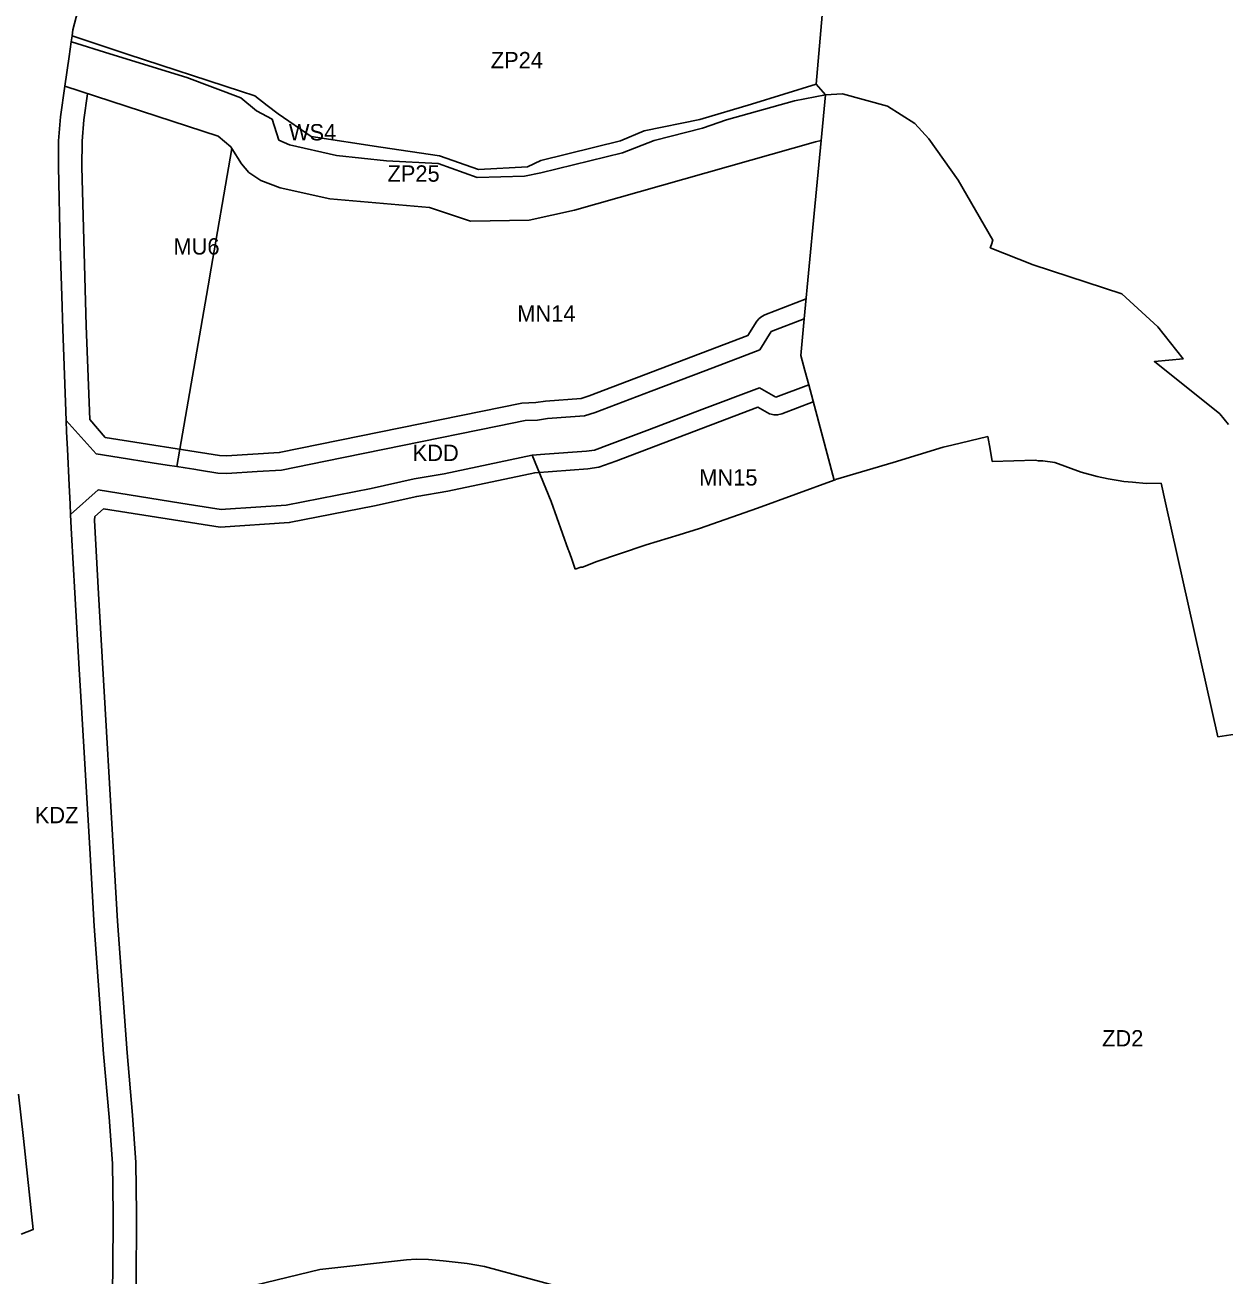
# Model space of a CAD drawing. Extents: x 7428103 to 7431580, y 5545880 to 5549002.
# Drawn here: x 7430217.3 to 7430624.7, y 5547815.6 to 5548240.3 of the extents above; entities that cross this region are included whole.
import ezdxf

# ---------------------------------------------------------------- set-up
doc = ezdxf.new("R2010")
doc.units = 0
for name, color, linetype in [('CZ_L_granica obszaru objętego planem', 7, 'Continuous'), ('CZ_L_linie rozgraniczające tereny o różnym przeznaczeniu oraz różnych warunkach ich zabudowy i zagospodarowania', 7, 'Continuous'), ('CZ_L_maksymalne nieprzekraczalne linie zabudowy', 7, 'Continuous'), ('CZ_L_opisy_linie rozgraniczające tereny o różnym przeznaczeniu oraz różnych warunkach ich zabudowy i zagospodarowania', 7, 'Continuous'), ('Łąki_Nowohuckie', 7, 'Continuous')]:
    doc.layers.add(name, color=color, linetype=linetype)

msp = doc.modelspace()

# ---------------------------------------------------------------- linework, layer by layer
at = {"layer": 'CZ_L_granica obszaru objętego planem'}
for p, q in [((7430488.2, 5548243.64), (7430486.07, 5548220.19)), ((7430486.07, 5548220.19), (7430489.28, 5548216.56)), ((7430489.28, 5548216.56), (7430495.05, 5548216.89)), ((7430495.05, 5548216.89), (7430510.4, 5548212.74)), ((7430510.4, 5548212.74), (7430519.59, 5548206.79)), ((7430519.59, 5548206.79), (7430524.41, 5548201.63)), ((7430524.41, 5548201.63), (7430534.41, 5548187.52)), ((7430534.41, 5548187.52), (7430546.11, 5548167.16)), ((7430546.11, 5548167.16), (7430545.74, 5548165.72)), ((7430545.74, 5548165.72), (7430545.28, 5548164.62)), ((7430545.28, 5548164.62), (7430559.83, 5548158.84)), ((7430559.83, 5548158.84), (7430590, 5548148.9)), ((7430590, 5548148.9), (7430602.17, 5548137.68)), ((7430602.17, 5548137.68), (7430610.8, 5548126.84)), ((7430610.8, 5548126.84), (7430601.08, 5548125.94)), ((7430601.08, 5548125.94), (7430623.24, 5548108.21)), ((7430623.24, 5548108.21), (7430626.18, 5548104.53))]:
    msp.add_line(p, q, dxfattribs=at)
at = {"layer": 'CZ_L_linie rozgraniczające tereny o różnym przeznaczeniu oraz różnych warunkach ich zabudowy i zagospodarowania'}
for p, q in [((7430233.55, 5548238.61), (7430238.48, 5548257.83)), ((7430232.97, 5548234.58), (7430233.26, 5548236.57)), ((7430233.26, 5548236.57), (7430233.55, 5548238.61)), ((7430252.35, 5548230.23), (7430233.26, 5548236.57)), ((7430232.97, 5548234.58), (7430232.26, 5548229.57)), ((7430233.12, 5548234.54), (7430232.97, 5548234.58)), ((7430246.11, 5548230.46), (7430233.12, 5548234.54)), ((7430232.26, 5548229.57), (7430230.82, 5548219.48)), ((7430272.28, 5548222.47), (7430246.11, 5548230.46)), ((7430290.55, 5548217.78), (7430252.35, 5548230.23)), ((7430290.62, 5548215.58), (7430272.28, 5548222.47)), ((7430229.35, 5548209.12), (7430230.82, 5548219.48)), ((7430230.82, 5548219.48), (7430282.93, 5548202.45)), ((7430486.13, 5548220.12), (7430464.19, 5548213.43)), ((7430295.41, 5548216.17), (7430290.55, 5548217.78)), ((7430295.89, 5548211.15), (7430290.62, 5548215.58)), ((7430299.61, 5548212.94), (7430295.41, 5548216.17)), ((7430478.71, 5548214.47), (7430455.63, 5548208)), ((7430489.27, 5548216.57), (7430478.71, 5548214.47)), ((7430301.22, 5548208.29), (7430295.89, 5548211.15)), ((7430303.31, 5548210.07), (7430299.61, 5548212.94)), ((7430314.49, 5548202.4), (7430303.31, 5548210.07)), ((7430464.19, 5548213.43), (7430446.59, 5548208.22)), ((7430228.71, 5548200.95), (7430229.35, 5548209.12)), ((7430303.53, 5548201.13), (7430301.22, 5548208.29)), ((7430446.59, 5548208.22), (7430427.65, 5548204.33)), ((7430447.53, 5548205.27), (7430431.02, 5548201.02)), ((7430455.63, 5548208), (7430447.53, 5548205.27)), ((7430228.61, 5548192.08), (7430228.71, 5548200.95)), ((7430282.93, 5548202.45), (7430287.24, 5548198.89)), ((7430307.2, 5548199.55), (7430303.53, 5548201.13)), ((7430338.22, 5548198.75), (7430314.49, 5548202.4)), ((7430419.63, 5548200.97), (7430392.56, 5548194.23)), ((7430427.65, 5548204.33), (7430419.63, 5548200.97)), ((7430431.02, 5548201.02), (7430420.33, 5548196.89)), ((7430485.47, 5548176.28), (7430487.81, 5548200.98)), ((7430485.88, 5548200.6), (7430487.81, 5548200.98)), ((7430287.61, 5548198.3), (7430279.97, 5548154.38)), ((7430287.24, 5548198.89), (7430287.61, 5548198.3)), ((7430287.61, 5548198.3), (7430290.85, 5548193.11)), ((7430323.17, 5548195.98), (7430307.2, 5548199.55)), ((7430358.09, 5548195.8), (7430338.22, 5548198.75)), ((7430420.33, 5548196.89), (7430392.56, 5548190.04)), ((7430404.03, 5548177.42), (7430485.88, 5548200.6)), ((7430290.85, 5548193.11), (7430293.36, 5548190.11)), ((7430340.16, 5548194.14), (7430323.17, 5548195.98)), ((7430357.69, 5548193.18), (7430340.16, 5548194.14)), ((7430370.96, 5548188.49), (7430357.69, 5548193.18)), ((7430371.33, 5548191.18), (7430358.09, 5548195.8)), ((7430392.56, 5548194.23), (7430388.01, 5548192.08)), ((7430229.26, 5548165.1), (7430228.61, 5548192.08)), ((7430293.36, 5548190.11), (7430297.44, 5548187.42)), ((7430387.02, 5548188.86), (7430370.96, 5548188.49)), ((7430388.01, 5548192.08), (7430371.33, 5548191.18)), ((7430392.56, 5548190.04), (7430387.02, 5548188.86)), ((7430297.44, 5548187.42), (7430303.93, 5548184.91)), ((7430303.93, 5548184.91), (7430320.84, 5548181.16)), ((7430320.84, 5548181.16), (7430354.72, 5548178.32)), ((7430354.72, 5548178.32), (7430368.63, 5548173.67)), ((7430388.61, 5548173.94), (7430404.03, 5548177.42)), ((7430482.08, 5548140.44), (7430485.47, 5548176.28)), ((7430368.63, 5548173.67), (7430388.61, 5548173.94)), ((7430229.77, 5548148.3), (7430229.26, 5548165.1)), ((7430279.96, 5548154.3), (7430268.81, 5548090.25)), ((7430279.97, 5548154.38), (7430279.92, 5548154.37)), ((7430279.92, 5548154.37), (7430279.96, 5548154.3)), ((7430230.12, 5548136.93), (7430229.77, 5548148.3)), ((7430482.08, 5548140.44), (7430470.86, 5548136.18)), ((7430481.61, 5548135.46), (7430482.08, 5548140.44)), ((7430231.27, 5548105.97), (7430230.12, 5548136.93)), ((7430470.86, 5548136.18), (7430466.93, 5548129.89)), ((7430480.91, 5548128.02), (7430481.61, 5548135.46)), ((7430466.93, 5548129.89), (7430461.04, 5548127.66)), ((7430461.04, 5548127.66), (7430448.61, 5548122.95)), ((7430482.28, 5548122.88), (7430480.91, 5548128.02)), ((7430448.61, 5548122.95), (7430430.03, 5548115.9)), ((7430483.58, 5548118.05), (7430482.28, 5548122.88)), ((7430447.29, 5548109.61), (7430466.82, 5548117.02)), ((7430466.82, 5548117.02), (7430472.36, 5548113.8)), ((7430472.36, 5548113.8), (7430483.58, 5548118.05)), ((7430492.28, 5548085.64), (7430483.58, 5548118.05)), ((7430430.03, 5548115.9), (7430411.01, 5548108.69)), ((7430407.42, 5548107.5), (7430402.63, 5548107.14)), ((7430411.01, 5548108.69), (7430407.42, 5548107.5)), ((7430429.43, 5548102.84), (7430447.29, 5548109.61)), ((7430241.51, 5548094.57), (7430231.27, 5548105.97)), ((7430231.27, 5548105.97), (7430231.41, 5548102.08)), ((7430377.82, 5548103.99), (7430345.54, 5548097.43)), ((7430387.18, 5548105.9), (7430377.82, 5548103.99)), ((7430391.43, 5548105.99), (7430387.18, 5548105.9)), ((7430394.78, 5548106.56), (7430391.43, 5548105.99)), ((7430402.63, 5548107.14), (7430394.78, 5548106.56)), ((7430231.41, 5548102.08), (7430231.56, 5548098.07)), ((7430415.89, 5548097.71), (7430429.43, 5548102.84)), ((7430532.22, 5548097.57), (7430544.48, 5548100.45)), ((7430544.48, 5548100.45), (7430545.19, 5548096.15)), ((7430231.56, 5548098.07), (7430231.66, 5548096.13)), ((7430231.66, 5548096.13), (7430232.27, 5548083.94)), ((7430345.54, 5548097.43), (7430319.42, 5548092.11)), ((7430393.97, 5548094.46), (7430408.06, 5548095.51)), ((7430408.06, 5548095.51), (7430410.8, 5548095.88)), ((7430410.8, 5548095.88), (7430415.89, 5548097.71)), ((7430512.25, 5548091.62), (7430529.32, 5548096.89)), ((7430529.32, 5548096.89), (7430532.22, 5548097.57)), ((7430545.19, 5548096.15), (7430545.89, 5548091.96)), ((7430249.28, 5548093.34), (7430241.51, 5548094.57)), ((7430260.49, 5548091.57), (7430249.28, 5548093.34)), ((7430265.53, 5548090.77), (7430260.49, 5548091.57)), ((7430268.81, 5548090.25), (7430265.53, 5548090.77)), ((7430319.42, 5548092.11), (7430304.47, 5548089.07)), ((7430359.72, 5548087.78), (7430389.57, 5548094.14)), ((7430389.57, 5548094.14), (7430393.97, 5548094.46)), ((7430389.57, 5548094.14), (7430396.08, 5548078.44)), ((7430492.67, 5548085.91), (7430512.25, 5548091.62)), ((7430545.89, 5548091.96), (7430560.7, 5548092.42)), ((7430560.7, 5548092.42), (7430561.51, 5548092.24)), ((7430561.51, 5548092.24), (7430563.18, 5548092.26)), ((7430563.18, 5548092.26), (7430567.21, 5548091.67)), ((7430567.21, 5548091.67), (7430576.13, 5548088.36)), ((7430271.74, 5548089.79), (7430268.81, 5548090.25)), ((7430274.65, 5548089.33), (7430271.74, 5548089.79)), ((7430276.62, 5548089.02), (7430274.65, 5548089.33)), ((7430282.85, 5548088.03), (7430276.62, 5548089.02)), ((7430285.84, 5548087.95), (7430282.85, 5548088.03)), ((7430296.15, 5548088.57), (7430285.84, 5548087.95)), ((7430304.47, 5548089.07), (7430296.15, 5548088.57)), ((7430349.53, 5548086.09), (7430359.72, 5548087.78)), ((7430576.13, 5548088.36), (7430581.65, 5548086.9)), ((7430581.65, 5548086.9), (7430585.38, 5548086.09)), ((7430232.27, 5548083.94), (7430232.59, 5548077.5)), ((7430232.76, 5548073.98), (7430242.14, 5548082.36)), ((7430242.14, 5548082.36), (7430270.17, 5548077.89)), ((7430306.04, 5548077.14), (7430334.93, 5548082.84)), ((7430334.93, 5548082.84), (7430349.53, 5548086.09)), ((7430466.14, 5548076.17), (7430492.28, 5548085.64)), ((7430492.28, 5548085.64), (7430492.7, 5548085.79)), ((7430492.7, 5548085.79), (7430492.67, 5548085.91)), ((7430585.38, 5548086.09), (7430588.71, 5548085.55)), ((7430588.71, 5548085.55), (7430590.63, 5548085.24)), ((7430590.63, 5548085.24), (7430593.66, 5548084.96)), ((7430593.66, 5548084.96), (7430598.23, 5548084.54)), ((7430598.23, 5548084.54), (7430603.38, 5548084.62)), ((7430603.38, 5548084.62), (7430604.88, 5548077.9)), ((7430270.17, 5548077.89), (7430282.49, 5548075.96)), ((7430396.08, 5548078.44), (7430401.89, 5548062.04)), ((7430604.88, 5548077.9), (7430622.64, 5547998.43)), ((7430232.59, 5548077.5), (7430232.76, 5548073.98)), ((7430232.88, 5548071.65), (7430232.76, 5548073.98)), ((7430282.49, 5548075.96), (7430284.1, 5548075.67)), ((7430284.1, 5548075.67), (7430285.38, 5548075.76)), ((7430285.38, 5548075.76), (7430295.73, 5548076.52)), ((7430295.73, 5548076.52), (7430306.04, 5548077.14)), ((7430446.5, 5548069.19), (7430466.14, 5548076.17)), ((7430233.12, 5548067.32), (7430232.88, 5548071.65)), ((7430234.21, 5548047.34), (7430233.12, 5548067.32)), ((7430428.35, 5548063.68), (7430439.52, 5548067.07)), ((7430439.52, 5548067.07), (7430446.5, 5548069.19)), ((7430401.89, 5548062.04), (7430402.05, 5548061.67)), ((7430402.05, 5548061.67), (7430402.93, 5548059.13)), ((7430419.28, 5548060.67), (7430428.35, 5548063.68)), ((7430402.93, 5548059.13), (7430403.85, 5548056.49)), ((7430406.7, 5548056.04), (7430411.57, 5548058.01)), ((7430411.57, 5548058.01), (7430419.28, 5548060.67)), ((7430403.85, 5548056.49), (7430404.21, 5548055.47)), ((7430404.21, 5548055.47), (7430406.11, 5548056.13)), ((7430406.11, 5548056.13), (7430406.7, 5548056.04)), ((7430235.7, 5548021.46), (7430234.21, 5548047.34)), ((7430236.46, 5548008.38), (7430235.7, 5548021.46)), ((7430239.25, 5547960.55), (7430236.46, 5548008.38)), ((7430622.64, 5547998.43), (7430669.36, 5548005.96)), ((7430240.79, 5547934.15), (7430239.25, 5547960.55)), ((7430243.98, 5547890.74), (7430240.79, 5547934.15)), ((7430245.88, 5547869.21), (7430243.98, 5547890.74)), ((7430246.99, 5547853.51), (7430245.88, 5547869.21)), ((7430247.21, 5547836.58), (7430246.99, 5547853.51)), ((7430247.08, 5547816.27), (7430247.21, 5547836.58)), ((7430247, 5547812.36), (7430247.08, 5547816.27))]:
    msp.add_line(p, q, dxfattribs=at)
for points in [[(7430488.2, 5548243.64), (7430486.07, 5548220.19), (7430486.13, 5548220.12)], [(7430486.13, 5548220.12), (7430489.27, 5548216.57)], [(7430487.81, 5548200.98), (7430489.28, 5548216.56), (7430489.27, 5548216.57)], [(7430489.27, 5548216.57), (7430489.28, 5548216.56), (7430495.05, 5548216.89), (7430510.4, 5548212.74), (7430519.59, 5548206.79), (7430524.41, 5548201.63), (7430534.41, 5548187.52), (7430546.11, 5548167.16), (7430545.74, 5548165.72), (7430545.28, 5548164.62), (7430559.83, 5548158.84), (7430590, 5548148.9), (7430602.17, 5548137.68), (7430610.8, 5548126.84), (7430601.08, 5548125.94), (7430623.24, 5548108.21), (7430626.18, 5548104.53)]]:
    msp.add_lwpolyline(points, dxfattribs=at)
at = {"layer": 'CZ_L_maksymalne nieprzekraczalne linie zabudowy'}
for points in [[(7430238.53, 5548216.86), (7430237.29, 5548208.02), (7430236.72, 5548200.81), (7430236.61, 5548192.14), (7430238.09, 5548138.02), (7430239.26, 5548106.24), (7430244.55, 5548100.16), (7430283.4, 5548094.02), (7430285.74, 5548093.95), (7430303.69, 5548095.03), (7430386.15, 5548111.81), (7430390.87, 5548111.98), (7430394.15, 5548112.52), (7430406.23, 5548113.43), (7430409, 5548114.34), (7430462.91, 5548134.79), (7430465.96, 5548139.64), (7430466.73, 5548140.53), (7430467.65, 5548141.25), (7430468.7, 5548141.78), (7430482.72, 5548147.19)], [(7430485.11, 5548112.22), (7430474.49, 5548108.19), (7430472.99, 5548107.83), (7430471.82, 5548107.82), (7430470.29, 5548108.17), (7430466.27, 5548110.4), (7430418.01, 5548092.09), (7430412.21, 5548090.04), (7430408.54, 5548089.53), (7430390.5, 5548088.19), (7430360.95, 5548081.91), (7430350.41, 5548080.14), (7430336.09, 5548076.95), (7430307.07, 5548071.23), (7430283.55, 5548069.7), (7430243.96, 5548075.93), (7430241.05, 5548073.33), (7430240.87, 5548072.06), (7430242.24, 5548047.09), (7430248.7, 5547935.84), (7430251.98, 5547891.1), (7430253.85, 5547869.91), (7430254.98, 5547853.87), (7430255.21, 5547836.54), (7430254.99, 5547811.64)], [(7430295.46, 5547812.22), (7430317.51, 5547817.49), (7430346.9, 5547820.84), (7430350.17, 5547821.01), (7430354.39, 5547820.91), (7430359.33, 5547820.51), (7430367.47, 5547819.51), (7430373.39, 5547818.56), (7430403.54, 5547810.34)]]:
    msp.add_lwpolyline(points, dxfattribs=at)
at = {"layer": 'Łąki_Nowohuckie'}
for p, q in [((7430486.07, 5548220.19), (7430488.2, 5548243.64)), ((7430489.28, 5548216.56), (7430486.07, 5548220.19)), ((7430495.05, 5548216.89), (7430489.28, 5548216.56)), ((7430510.4, 5548212.74), (7430495.05, 5548216.89)), ((7430519.59, 5548206.79), (7430510.4, 5548212.74)), ((7430524.41, 5548201.63), (7430519.59, 5548206.79)), ((7430534.41, 5548187.52), (7430524.41, 5548201.63)), ((7430546.11, 5548167.16), (7430534.41, 5548187.52)), ((7430545.74, 5548165.72), (7430546.11, 5548167.16)), ((7430545.28, 5548164.62), (7430545.74, 5548165.72)), ((7430559.83, 5548158.84), (7430545.28, 5548164.62)), ((7430590, 5548148.9), (7430559.83, 5548158.84)), ((7430602.17, 5548137.68), (7430590, 5548148.9)), ((7430610.8, 5548126.84), (7430602.17, 5548137.68)), ((7430601.08, 5548125.94), (7430610.8, 5548126.84)), ((7430623.24, 5548108.21), (7430601.08, 5548125.94)), ((7430626.18, 5548104.53), (7430623.24, 5548108.21))]:
    msp.add_line(p, q, dxfattribs=at)
msp.add_lwpolyline([(7430215.11, 5547877.13), (7430216.71, 5547862.02), (7430219.99, 5547831.09), (7430215.97, 5547829.51)], dxfattribs=at)

# ---------------------------------------------------------------- texts
at = {"layer": 'CZ_L_opisy_linie rozgraniczające tereny o różnym przeznaczeniu oraz różnych warunkach ich zabudowy i zagospodarowania'}
for s, p in [('ZP24', (7430375.55, 5548225.56)), ('WS4', (7430306.94, 5548201.06)), ('ZP25', (7430340.45, 5548187.04)), ('MU6', (7430267.71, 5548162.29)), ('MN14', (7430384.54, 5548139.49)), ('KDD', (7430349, 5548092.15)), ('MN15', (7430446.38, 5548083.82)), ('KDZ', (7430220.59, 5547969.11)), ('ZD2', (7430583.28, 5547893.29))]:
    msp.add_text(s, height=5.549, dxfattribs=at).set_placement(p)

doc.saveas('drawing.dxf')
